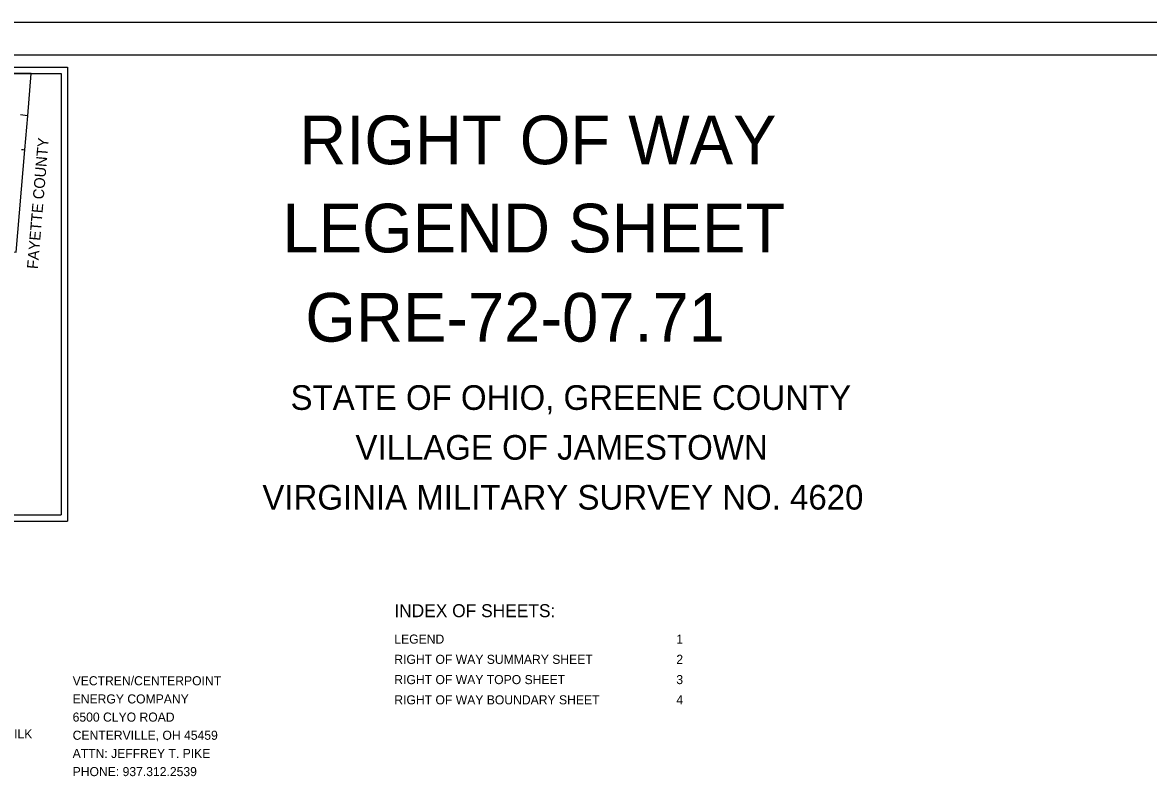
# Model space of a CAD drawing. Extents: x -13.9 to 69.1, y -25.2 to 26.1.
# Drawn here: x 7.96 to 25.31, y 10.32 to 22 of the extents above; entities that cross this region are included whole.
import ezdxf

# ---------------------------------------------------------------- set-up
doc = ezdxf.new("R2010")
doc.units = 0
for name, color, linetype in [('GM_X_Adjacent_County_Text', 7, 'Continuous'), ('GM_X_Township', 7, 'Continuous'), ('GM_X_Township_Road', 7, 'Continuous'), ('SH_Border', 7, 'Continuous'), ('SH_Cut_Line', 7, 'Continuous'), ('SH_Data', 7, 'Continuous'), ('SH_Text', 7, 'Continuous')]:
    doc.layers.add(name, color=color, linetype=linetype)

msp = doc.modelspace()

# ---------------------------------------------------------------- linework, layer by layer
at = {"layer": 'GM_X_Township'}
msp.add_lwpolyline([(8.098, 21.214), (2.668, 21.214), (2.571, 21.125), (2.538, 21.093), (2.521, 21.077), (2.928, 20.528), (2.315, 19.994), (2.335, 19.992), (2.419, 19.989), (2.469, 19.987), (2.518, 19.987), (2.6, 20.012), (2.571, 18.902), (4.529, 18.782), (7.866, 18.459), (7.999, 20.038), (8.043, 20.562)], close=True, dxfattribs=at)
at = {"layer": 'GM_X_Township_Road'}
for points in [[(7.93, 20.582), (7.969, 20.577), (8.004, 20.573), (8.044, 20.568)], [(7.949, 20.044), (7.975, 20.041), (7.999, 20.039)]]:
    msp.add_lwpolyline(points, dxfattribs=at)
at = {"layer": 'SH_Border'}
msp.add_lwpolyline([(1.5, 21.5), (33.5, 21.5), (33.5, 0.5), (1.5, 0.5)], close=True, dxfattribs=at)
at = {"layer": 'SH_Cut_Line'}
msp.add_lwpolyline([(0, 0), (34, 0), (34, 22), (0, 22)], close=True, dxfattribs=at)
at = {"layer": 'SH_Data'}
for p, q in [((1.657, 21.314), (8.657, 21.314)), ((1.757, 21.214), (8.557, 21.214)), ((8.557, 21.214), (8.557, 14.414)), ((8.657, 21.314), (8.657, 14.314)), ((1.757, 14.414), (8.557, 14.414)), ((1.657, 14.314), (8.657, 14.314))]:
    msp.add_line(p, q, dxfattribs=at)

# ---------------------------------------------------------------- texts
at = {"layer": 'GM_X_Adjacent_County_Text'}
msp.add_text('FAYETTE COUNTY', height=0.1686, rotation=85.1664, dxfattribs=at).set_placement((8.198, 18.196))
at = {"layer": 'SH_Data'}
for s, height, p in [('RIGHT OF WAY', 0.75, (12.227, 19.816)), ('LEGEND SHEET', 0.75, (11.968, 18.457)), (' GRE-72-07.71', 0.75, (12.042, 17.082)), ('           STATE OF OHIO, GREENE COUNTY           ', 0.38, (10.54, 16.03)), ('  VILLAGE OF JAMESTOWN ', 0.38, (12.811, 15.262)), ('         VIRGINIA MILITARY SURVEY NO. 4620        ', 0.38, (10.388, 14.493)), ('INDEX OF SHEETS:', 0.2, (13.692, 12.835)), ('LEGEND                             ', 0.14, (13.692, 12.427)), ('1     ', 0.14, (18.038, 12.427)), ('RIGHT OF WAY SUMMARY SHEET         ', 0.14, (13.692, 12.115)), ('2     ', 0.14, (18.038, 12.115)), ('RIGHT OF WAY TOPO SHEET            ', 0.14, (13.692, 11.803)), ('3     ', 0.14, (18.038, 11.803)), ('RIGHT OF WAY BOUNDARY SHEET        ', 0.14, (13.692, 11.491)), ('4     ', 0.14, (18.038, 11.491))]:
    msp.add_text(s, height=height, dxfattribs=at).set_placement(p)
at = {"layer": 'SH_Text'}
for s, p in [('VECTREN/CENTERPOINT ', (8.735, 11.785)), ('ENERGY COMPANY', (8.735, 11.505)), ('6500 CLYO ROAD', (8.735, 11.225)), ('ATTN: HOWARD LAUDERMILK', (5.42, 10.966)), ('CENTERVILLE, OH 45459', (8.735, 10.945)), ('ATTN: JEFFREY T. PIKE', (8.735, 10.665)), ('PHONE: 937.312.2539', (8.735, 10.385))]:
    msp.add_text(s, height=0.14, dxfattribs=at).set_placement(p)

doc.saveas('drawing.dxf')
